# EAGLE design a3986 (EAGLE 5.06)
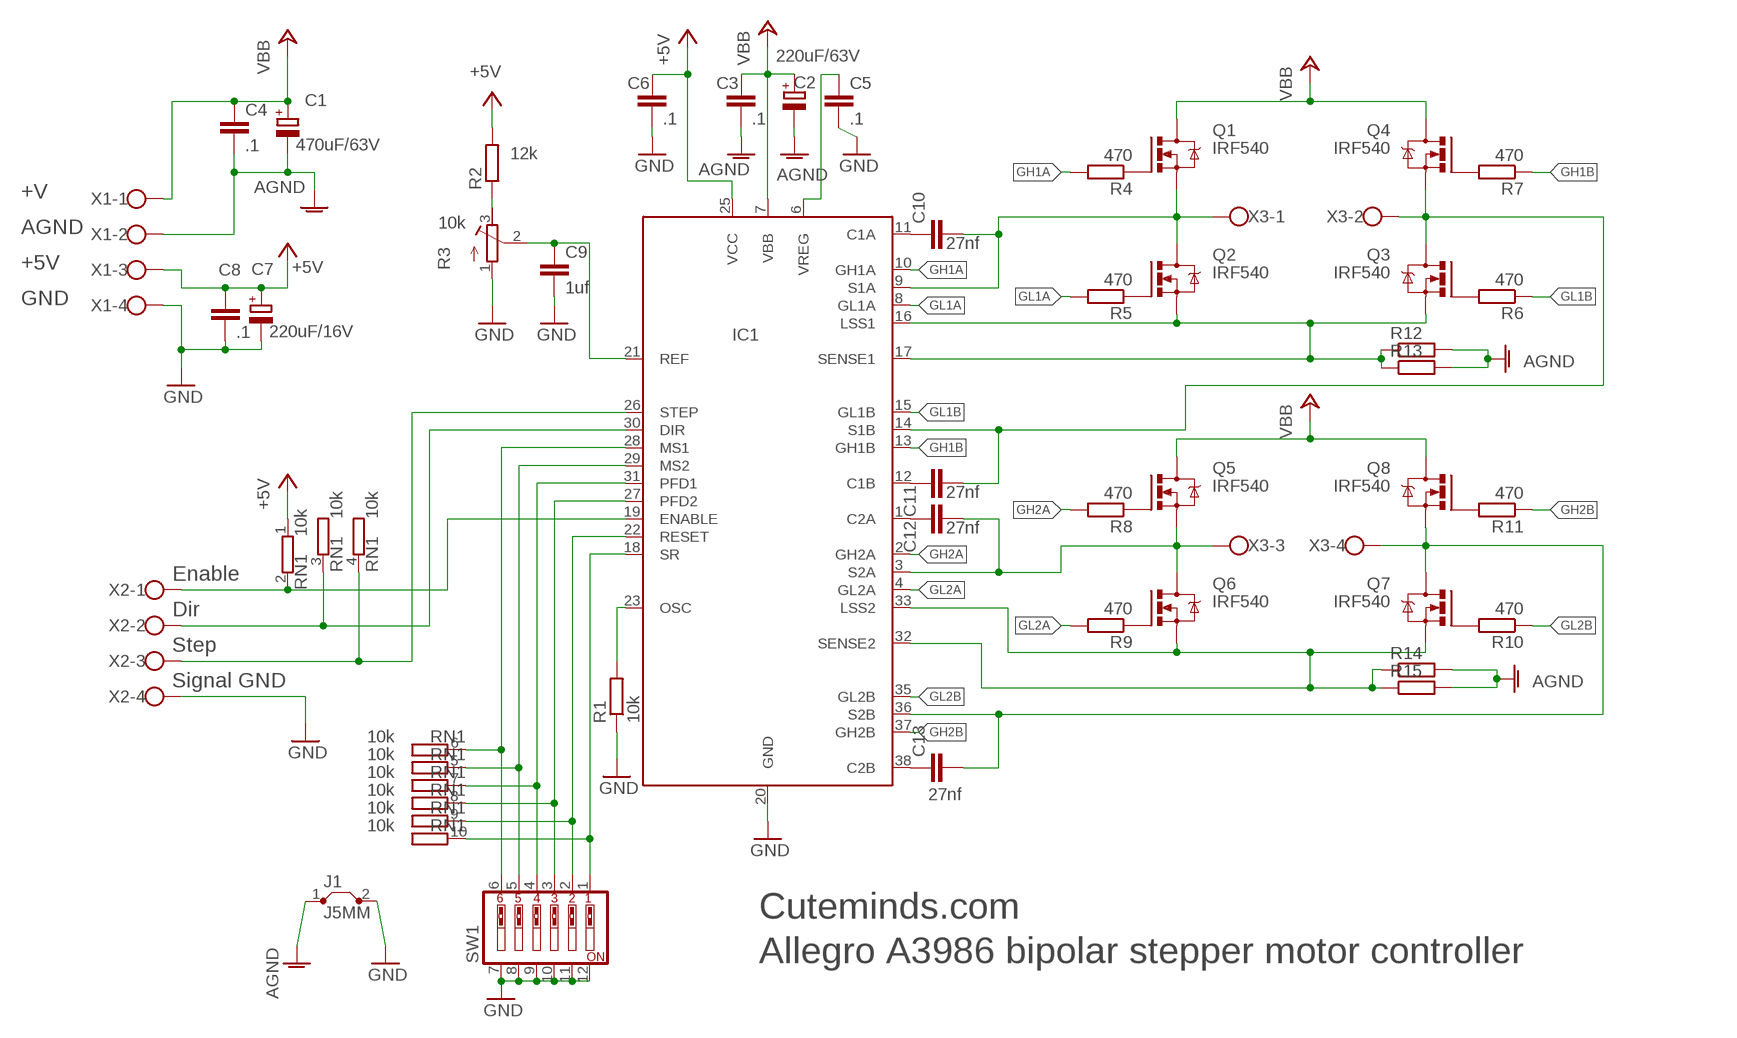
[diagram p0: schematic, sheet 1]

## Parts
C1  470uF/63V  CPOL-EUE5-10.5  [E5-10,5]
C2  220uF/63V  CPOL-EUE5-10.5  [E5-10,5]
C3  .1  C-EU050-024X044  [C050-024X044]
C4  .1  C-EU050-024X044  [C050-024X044]
C5  .1  C-EU050-024X044  [C050-024X044]
C6  .1  C-EU050-024X044  [C050-024X044]
C7  220uF/16V  CPOL-EUE5-8.5  [E5-8,5]
C8  .1  C-EU050-024X044  [C050-024X044]
C9  1uf  C-EU050-024X044  [C050-024X044]
C10  27nf  C-EU050-024X044  [C050-024X044]
C11  27nf  C-EU050-024X044  [C050-024X044]
C12  27nf  C-EU050-024X044  [C050-024X044]
C13  27nf  C-EU050-024X044  [C050-024X044]
IC1  A3986  [TSSOP38]
J1  J5MM  [05]
Q1  IRF540  [TO220BV]
Q2  IRF540  [TO220BV]
Q3  IRF540  [TO220BV]
Q4  IRF540  [TO220BV]
Q5  IRF540  [TO220BV]
Q6  IRF540  [TO220BV]
Q7  IRF540  [TO220BV]
Q8  IRF540  [TO220BV]
R1  10k  R-EU_0204/5  [0204/5]
R2  12k  R-EU_0204/5  [0204/5]
R3  10k  R-TRIMM64P  [RTRIM64P]
R4  470  R-EU_0204/5  [0204/5]
R5  470  R-EU_0204/5  [0204/5]
R6  470  R-EU_0204/5  [0204/5]
R7  470  R-EU_0204/5  [0204/5]
R8  470  R-EU_0204/5  [0204/5]
R9  470  R-EU_0204/5  [0204/5]
R10  470  R-EU_0204/5  [0204/5]
R11  470  R-EU_0204/5  [0204/5]
R12  R-EU_0207/15  [0207/15]
R13  R-EU_0207/15  [0207/15]
R14  R-EU_0207/15  [0207/15]
R15  R-EU_0207/15  [0207/15]
RN1  10k  GE09RP  [SIL10]
SW1  SW_DIP-6  [EDG-06]
X1  W237-4  [W237-4]
X2  W237-4  [W237-4]
X3  W237-4  [W237-4]

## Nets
+5V [5V]: C6.1 C7.+ C8.1 IC1.25(VCC) R2.2 RN1.1 X1.3
+24V [V+]: C1.+ C2.+ C3.1 C4.1 IC1.7(VBB) Q1.D Q4.D Q5.D Q8.D X1.1 ; supply symbol labelled VBB
AGND [AGND]: C1.- C2.- C3.2 C4.2 J1.1 R12.2 R13.2 R14.2 R15.2 X1.2
GH1A: IC1.10(GH1A) R4.2
GH1B: IC1.13(GH1B) R7.1
GH2A: IC1.2(GH2A) R8.2
GH2B: IC1.37(GH2B) R11.1
GL1A: IC1.8(GL1A) R5.2
GL1B: IC1.15(GL1B) R6.1
GL2A: IC1.4(GL2A) R9.2
GL2B: IC1.35(GL2B) R10.1
GND [GND]: C5.2 C6.2 C7.- C8.2 C9.2 IC1.20(GND) J1.2 R1.1 R3.1(E) SW1.7 SW1.8 SW1.9 SW1.10 SW1.11 SW1.12 X1.4 X2.4
N$1: IC1.27(PFD2) RN1.8 SW1.3
N$2: R2.1 R3.3(A)
N$3: IC1.28(MS1) RN1.6 SW1.6
N$4: C9.1 IC1.21(REF) R3.2(S)
N$5: IC1.29(MS2) RN1.5 SW1.5
N$6: IC1.23(OSC) R1.2
N$7: C5.1 IC1.6(VREG)
N$8: IC1.31(PFD1) RN1.7 SW1.4
N$10 [Motor]: IC1.16(LSS1) IC1.17(SENSE1) Q2.S Q3.S R12.1 R13.1
N$11 [Motor]: IC1.32(SENSE2) IC1.33(LSS2) Q6.S Q7.S R14.1 R15.1
N$12: Q1.G R4.1
N$13: Q2.G R5.1
N$14: Q3.G R6.2
N$15: Q4.G R7.2
N$16: Q5.G R8.1
N$17: IC1.18(SR) RN1.10 SW1.1
N$18: Q6.G R9.1
N$19: IC1.22(RESET) RN1.9 SW1.2
N$20: Q7.G R10.2
N$21: Q8.G R11.2
N$22: IC1.26(STEP) RN1.4 X2.3
N$23 [Motor]: C10.2 IC1.9(S1A) Q1.S Q2.D X3.1
N$24: IC1.30(DIR) RN1.3 X2.2
N$25: IC1.19(ENABLE) RN1.2 X2.1
N$26 [Motor]: C11.2 IC1.14(S1B) Q3.D Q4.S X3.2
N$27 [Motor]: C12.2 IC1.3(S2A) Q5.S Q6.D X3.3
N$28 [Motor]: C13.2 IC1.36(S2B) Q7.D Q8.S X3.4
N$30: C10.1 IC1.11(C1A)
N$31: C11.1 IC1.12(C1B)
N$32: C12.1 IC1.1(C2A)
N$33: C13.1 IC1.38(C2B)

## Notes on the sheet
- +V
- AGND
- +5V
- GND
- Enable
- Dir
- Step
- Signal GND
- Cuteminds.com
- Allegro A3986 bipolar stepper motor controller

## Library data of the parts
C1 C2 = resistor:CPOL-EU: POLARIZED CAPACITOR, European symbol
C3-C6 C8-C13 = resistor:C-EU: CAPACITOR, European symbol
C7 = rcl:CPOL-EU: POLARIZED CAPACITOR, European symbol
IC1 = allegro2:A3986: Dual Full-Bridge MOSFET Driver with Microstepping Translator
J1 = jumper:J: Bridge
Q1-Q8 = transistor-power:IRF540: HEXFET Power MOSFET
R1 R2 R4-R15 = rcl:R-EU_: RESISTOR, European symbol
R3 = rcl:R-TRIMM: Trimm resistor
RN1 = resistor-sil:GE09RP: SIL RESISTOR
SW1 = special:SW_DIP-6: DIP SWITCH
X1-X3 = con-wago-500:W237-4: WAGO SCREW CLAMP

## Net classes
1 V+: width 1.27 mm
2 GND: width 0.508 mm
3 AGND: width 1.778 mm
4 Motor: width 1.27 mm
5 5V: width 0.61 mm
6 none1: width 0.406 mm
7 none2: width 0.406 mm

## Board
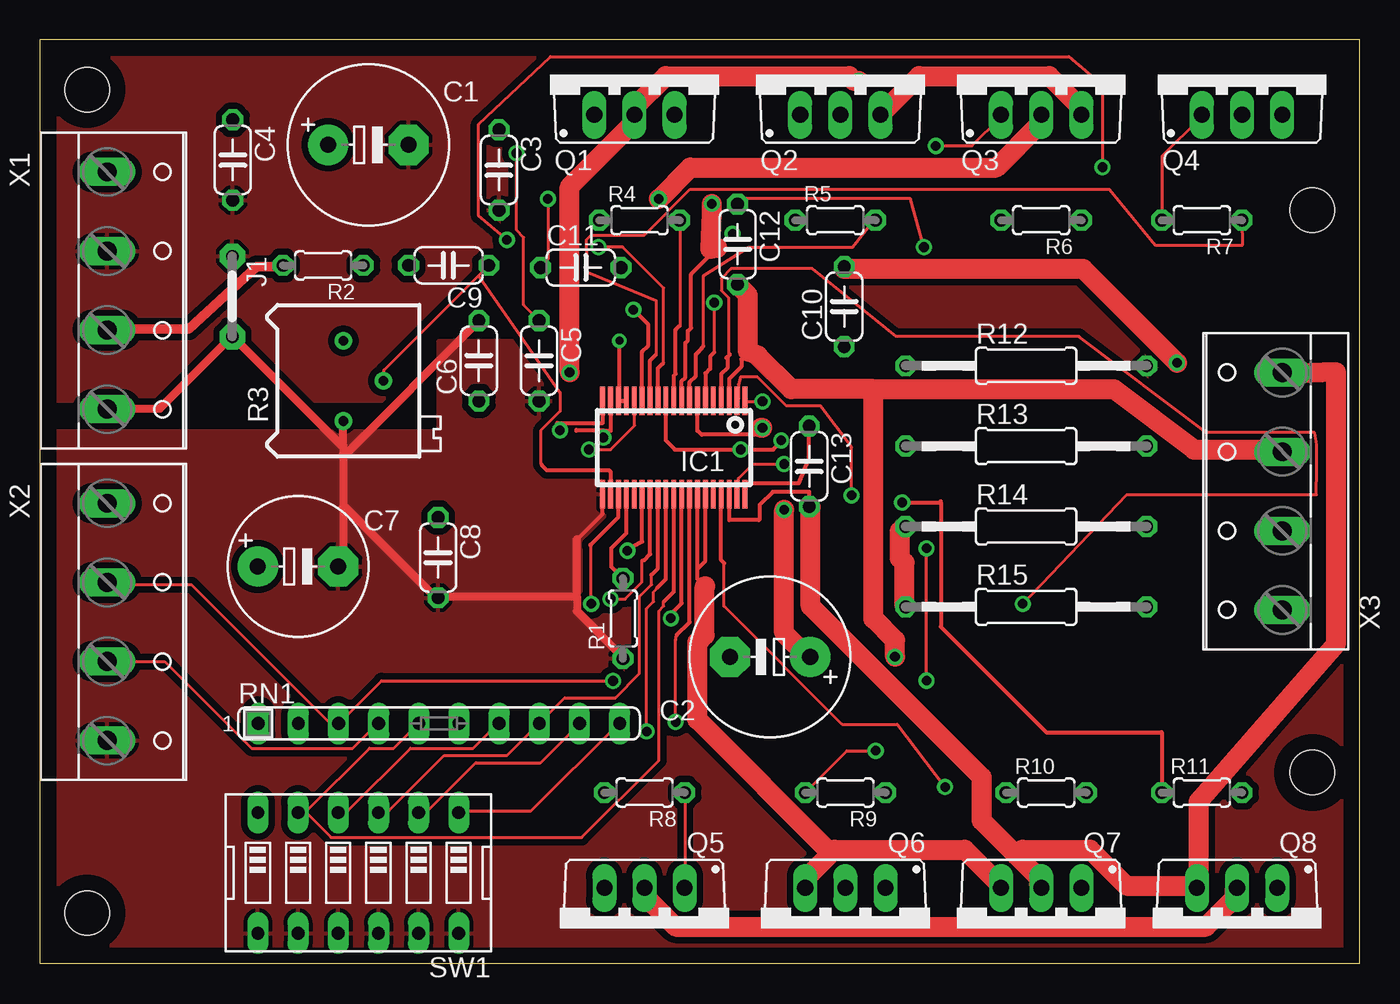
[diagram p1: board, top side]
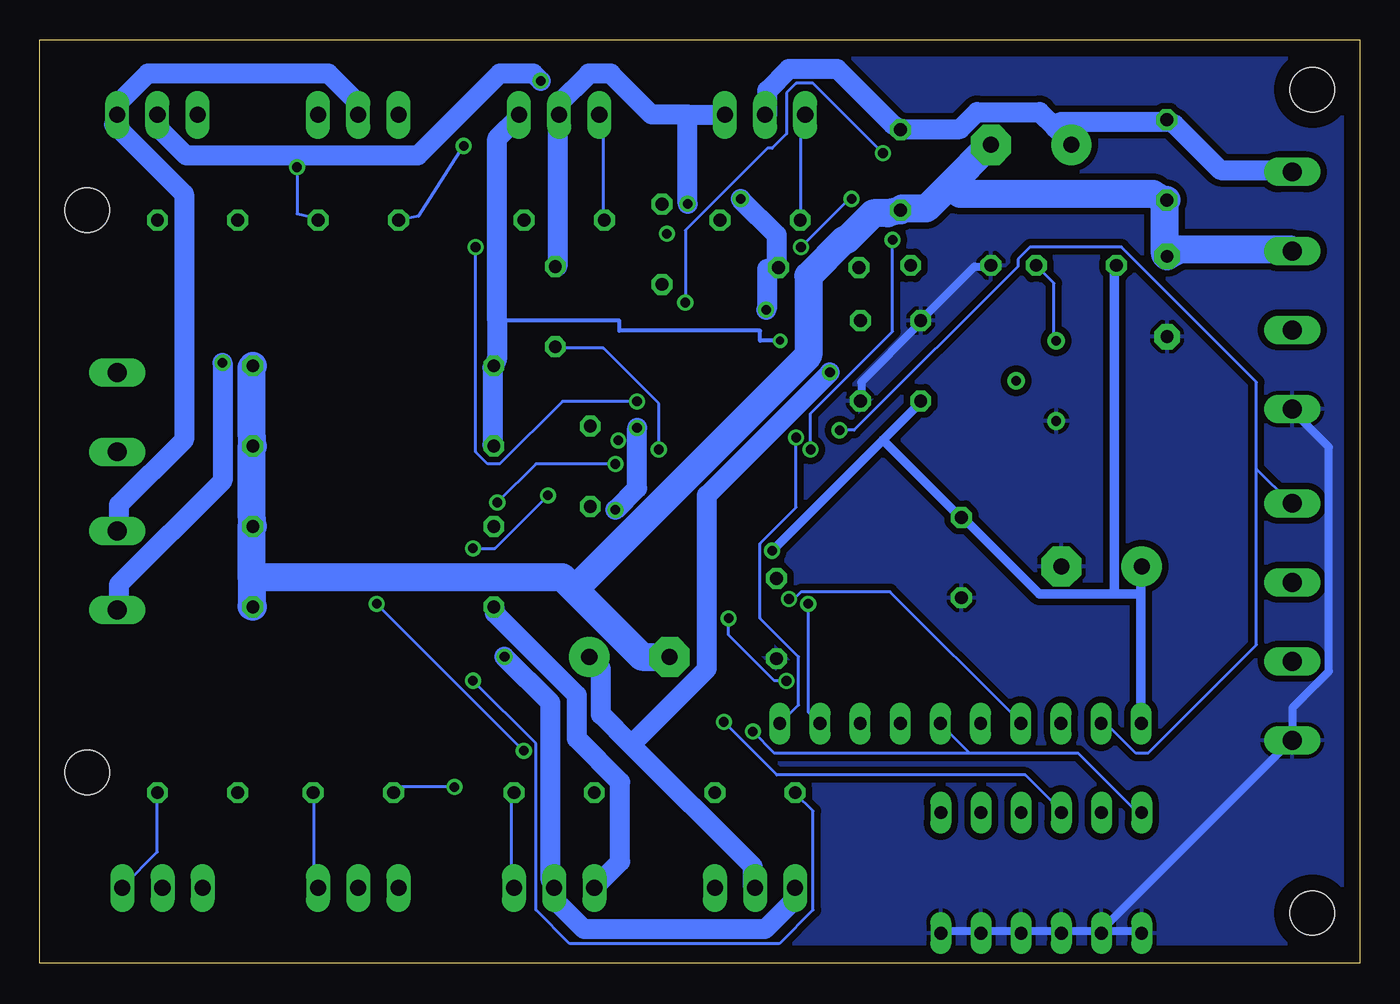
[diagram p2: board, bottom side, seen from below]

Size 83.49 x 58.41 mm. Coordinates in mm from the lower left corner, seen from the top.
Outline: 0,0 83.49,0 83.49,58.41 0,58.41 0,0
Copper layers (1*16): Top 0.035mm / dielectric 1.5mm / Bottom 0.035mm
Design rules "default *": minimum track width 8mil, minimum drill 24mil, track to track 6mil, track to pad 6mil, pad to pad 6mil, via to via 6mil, smd to smd 12mil, copper to edge 40mil, drill to drill 8mil, minimum pad ring 10mil, minimum via ring 8mil, stop-mask expansion 4mil, vias tented up to drill 0mil, thermal gap 10mil
Holes 2.8 mm at 3.01,55.24 80.48,47.62 80.48,12.06 3.01,3.17

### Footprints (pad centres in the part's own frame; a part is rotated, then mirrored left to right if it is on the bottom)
E5-10,5 = drill 1.016 pad 2.54 round: + -2.54,0 | drill 1.016 pad 2.54 octagon: - 2.54,0
C050-024X044 = drill 0.813 octagon: 1 -2.54,0; 2 2.54,0
E5-8,5 = drill 1.016 pad 2.54 round: + -2.54,0 | drill 1.016 pad 2.54 octagon: - 2.54,0
TSSOP38 = smd 0.3 x 1.8: 1 0,0; 2 0.5,0; 3 1,0; 4 1.5,0; 5 2,0; 6 2.5,0; 7 3,0; 8 3.5,0; 9 4,0; 10 4.5,0; 11 5,0; 12 5.5,0; 13 6,0; 14 6.5,0; 15 7,0; 16 7.5,0; 17 8,0; 18 8.5,0; 19 9,0; 20 9,5.9; 21 8.5,5.9; 22 8,5.9; 23 7.5,5.9; 24 7,5.9; 25 6.5,5.9; 26 6,5.9; 27 5.5,5.9; 28 5,5.9; 29 4.5,5.9; 30 4,5.9; 31 3.5,5.9; 32 3,5.9; 33 2.5,5.9; 34 2,5.9; 35 1.5,5.9; 36 1,5.9; 37 0.5,5.9; 38 0,5.9
05 = drill 0.813 pad 1.6 octagon: 1 -2.54,0; 2 2.54,0
TO220BV = drill 1.016 long: D 0,-2.54; G -2.54,-2.54; S 2.54,-2.54
0204/5 = drill 0.813 octagon: 1 -2.54,0; 2 2.54,0
RTRIM64P = drill 0.61 round: 1 0,-2.54; 2 2.54,0; 3 0,2.54
0207/15 = drill 0.813 octagon: 1 -7.62,0; 2 7.62,0
SIL10 = drill 0.813 long: 1 -11.43,0; 2 -8.89,0; 3 -6.35,0; 4 -3.81,0; 5 -1.27,0; 6 1.27,0; 7 3.81,0; 8 6.35,0; 9 8.89,0; 10 11.43,0
EDG-06 = drill 0.813 long: 1 -6.35,-3.81; 2 -3.81,-3.81; 3 -1.27,-3.81; 4 1.27,-3.81; 5 3.81,-3.81; 6 6.35,-3.81; 7 6.35,3.81; 8 3.81,3.81; 9 1.27,3.81; 10 -1.27,3.81; 11 -3.81,3.81; 12 -6.35,3.81
W237-4 = drill 1.194 long: 1 -7.5,-1.27; 2 -2.5,-1.27; 3 2.5,-1.27; 4 7.5,-1.27

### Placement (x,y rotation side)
C1  20.79,51.75 0 top
C2  46.19,19.36 180 top
C3  29.05,50.16 270 top
C4  12.22,50.8 270 top
C5  31.59,38.1 270 top
C6  27.78,38.1 90 top
C7  16.35,25.08 0 top
C8  25.2,25.65 270 top
C9  25.87,44.13 180 top
C10  50.88,41.52 90 top
C11  34.22,43.99 0 top
C12  44.14,45.46 270 top
C13  48.67,31.42 270 top
IC1  44.6,35.55 180 top
J1  12.19,42.16 270 top
Q1  37.62,56.19 0 top
Q2  50.63,56.19 0 top
Q3  63.34,56.19 0 top
Q4  76.03,56.19 0 top
Q5  38.25,2.22 180 top
Q6  50.95,2.22 180 top
Q7  63.34,2.22 180 top
Q8  75.72,2.22 180 top
R1  36.88,21.8 90 top
R2  17.93,44.13 180 top
R3  19.2,36.83 0 top
R4  37.94,46.98 0 top
R5  50.32,46.98 0 top
R6  63.34,46.98 180 top
R7  73.49,46.98 180 top
R8  38.25,10.79 180 top
R9  50.95,10.79 180 top
R10  63.65,10.79 0 top
R11  73.49,10.79 0 top
R12  62.38,37.78 0 top
R13  62.38,32.7 0 top
R14  62.38,27.62 0 top
R15  62.38,22.54 0 top
RN1  25.25,15.16 0 top
SW1  20.16,5.71 180 top
X1  5.55,42.54 270 top
X2  5.55,21.58 270 top
X3  77.3,29.84 90 top

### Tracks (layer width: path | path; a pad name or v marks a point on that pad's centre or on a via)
+5V  (via drill 0.61)
  Top 0.254: IC1.25 38.1,26.66 37.09,26.13
  Top 0.61: R2.2 15.38,44.06 13.72,44.06 9.44,40.1 4.41,40.1 X1.3 | v37.17,26.08 37.22,26.08 37.09,26.13
  Bottom 0.61: 13.86,23.34 13.86,25.01 C7.+ | 13.86,23.34 13.86,15.26 RN1.1 | 30.16,33.09 27.72,35.53 C6.1 | 30.16,33.09 v37.17,26.08 | 30.16,33.09 25.29,28.21 C8.1 24.98,28.06 20.26,23.34 15.53,23.34 | 13.86,23.34 15.53,23.34 | R2.2 15.53,44.06 15.53,23.34
+24V  (via drill 0.61)
  Top 0.254: IC1.7 41.6,33.68 41.86,33.43 45.18,33.43 45.63,33.87
  Top 1.27: v47.08,28.67 47.08,20.9 48.6,19.38 C2.+ | v45.71,33.85 45.63,33.87 | Q8.D 75.58,4.75 75.58,4.13 73.75,2.31 40.22,2.31 38.39,4.13 38.39,4.75 Q5.D | v51.8,55.8 51.5,55.8 51.19,56.1 39.61,56.1 37.63,54.12 37.63,53.66 Q1.D 37.48,53.06 33.52,49.09 v33.52,37.36
  Bottom 1.27: v45.71,33.85 45.71,30.04 v47.08,28.67 | 46.09,13.81 47.99,15.72 47.99,18.61 48.6,19.22 C2.+ | 46.09,13.81 38.39,6.12 38.39,4.9 Q5.D | 19.27,52.83 18.28,51.84 C1.+ | 19.27,52.83 20.26,53.82 24.22,53.82 25.29,52.75 28.94,52.75 C3.1 29.55,53.06 33.06,56.56 36.11,56.56 37.48,55.19 37.48,53.66 Q1.D | 19.27,52.83 18.89,53.21 12.33,53.21 C4.1 11.72,53.06 8.83,50.16 4.41,50.16 X1.1 | v51.8,55.8 52.26,56.26 54.39,56.26 59.58,51.07 74.21,51.07 76.03,52.9 Q4.D | v33.52,37.36 41.29,29.59 41.29,18.61 46.09,13.81
AGND
  Bottom 1.778: 12.33,48.18 12.33,44.83 J1.1 11.42,45.13 4.41,45.13 X1.2 | 12.33,48.18 C4.2 | 25.89,49.25 23.46,51.68 C1.- | 25.89,49.25 27.42,47.72 28.94,47.72 C3.2 29.86,47.42 30.77,47.42 32.45,45.74 32.6,45.74 34.89,43.45 34.89,38.43 49.67,23.64 | 12.33,48.18 13.09,48.64 25.29,48.64 25.89,49.25 | 70.09,24.4 70.09,27.61 R14.2 70.09,28.37 70.09,32.63 R13.2 70.09,33.55 70.09,37.66 R12.2 | 70.09,24.4 70.09,22.58 R15.2 | 49.67,23.64 50.43,24.4 70.09,24.4 | 49.67,23.64 45.4,19.38 43.73,19.38 C2.-
  pour Top (isolate 0.406): 1.1,57.78 83.02,57.78 83.02,35.55 1.1,35.55
GH1A
  Top 0.203: 40.48,40.31 40.53,40.41 40.53,46.96 R4.2
  Top 0.254: IC1.10 40.1,37.15 40.22,37.27 40.22,40.05 40.48,40.31
GH1B
  Top 0.203: 38.95,38.45 39,38.43 39,41.88 34.65,43.67 34.58,45.74 34.89,46.05 38.24,46.05 41.13,48.94 67.65,48.94 70.55,45.41 76.07,45.41 76.03,46.96 R7.1
  Top 0.254: IC1.13 38.6,38.11 38.95,38.45
GH2A  (via drill 0.61)
  Top 0.203: v51.35,29.59 51.35,32.63 49.38,35.24 47.22,35.24 45.39,37.07 44.34,37.07 44.18,36.6 44.18,35.68 IC1.2 | v56.08,17.86 v56.08,26.23
  Bottom 0.203: v51.35,29.59 54.7,26.23 v56.08,26.23 | v56.08,17.86 52.11,13.89 52.11,3.37 49.98,1.24 36.72,1.24 34.58,3.37 34.58,9.62 35.65,10.69 R8.2
GH2B  (via drill 0.61)
  Top 0.203: v47.08,31.57 45.1,31.57 44.18,30.65 44.18,29.74 IC1.37 | R11.1 70.85,10.84
  Top 0.254: v54.55,29.13 56.98,29.13 | 56.98,29.13 56.98,29.2 | 56.98,29.13 56.98,21.27 63.65,14.6 70.95,14.6 R11.1
  Bottom 0.203: v47.08,31.57 52.11,31.57 v54.55,29.13
GL1A
  Top 0.203: 41.97,39.03 41.97,43.47 44.86,45.27 51.41,45.27 52.72,46.96 R5.2
  Top 0.254: IC1.8 41.1,36.73 41.51,37.14 41.51,38.49 41.97,39.03 41.6,38.59
GL1B  (via drill 0.61)
  Top 0.203: v34.73,32.48 36.11,32.48 37.63,34.01 37.63,35.53 IC1.15 | v29.55,45.74 27.77,47.26 27.77,53.06 32.31,57.34 65.07,57.34 67.21,55.52 v67.21,50.34
  Bottom 0.203: v34.73,32.48 34.73,34.77 29.55,39.95 v29.55,45.74 | v67.21,50.34 67.21,47.39 65.98,47.11 R6.1
GL2A  (via drill 0.61)
  Top 0.203: v62.17,22.73 68.74,29.62 80.73,29.62 80.76,31.24 80.76,32.79 80.63,33.55 73.79,33.55 65.73,39.62 54.19,39.62 48.88,43.91 43.73,43.91 43.12,43.3 43.12,42.54 43.57,42.08 43.57,38.58 43.66,38.5 | v52.87,13.43 51.04,13.43 48.45,10.84 R9.2
  Top 0.254: IC1.4 43.1,37.24 43.49,37.62 43.49,38.33 43.66,38.5 43.43,38.27
  Bottom 0.203: v52.87,13.43 v62.17,22.73
GL2B  (via drill 0.61)
  Top 0.203: v57.25,11.15 54.24,15.11 50.74,15.11 43.27,22.58 43.27,25.17 43.3,25.29
  Top 0.254: IC1.35 43.1,25.48 43.3,25.29
  Bottom 0.203: v57.25,11.15 60.8,11.15 61.1,10.84 R10.1
GND
  Top 0.254: IC1.20 35.6,28.42 33.98,26.79
  Top 0.508: 33.97,23.18 33.97,22.27 36.87,19.38 R1.1 | 33.97,23.18 33.97,26.69 33.98,26.79 | 33.97,23.18 25.29,23.18 C8.2 24.98,23.18 19.34,28.82 19.19,28.82 | 19.19,28.82 19.19,25.47 18.89,25.17 C7.- | 19.19,32.18 19.19,28.82 | 19.19,32.79 19.19,32.18 | 19.19,32.79 19.19,34.16 R3.1 | 19.19,32.79 19.04,32.79 12.33,39.49 J1.2 12.03,39.49 7.61,35.07 4.41,35.07 X1.4 | C6.2 27.72,40.56 19.34,32.18 19.19,32.18
  Bottom 0.508: SW1.7 13.86,2 16.29,2 SW1.8 | SW1.8 16.45,2 18.89,2 SW1.9 19.04,2 21.32,2 SW1.10 21.63,2 23.91,2 SW1.11 24.07,2 26.51,2 SW1.12 | SW1.8 16.29,2.15 4.41,14.04 X2.4 4.25,14.35 4.25,16.18 1.97,18.46 1.97,32.63 4.25,34.92 X1.4 | C9.2 23.46,44.06 24.37,44.06 27.72,40.71 C6.2 27.88,40.41 31.53,36.75 31.53,35.68 C5.2
  pour Top (isolate 0.406): 1.1,33.65 25.23,33.65 25.23,39.37 83.02,39.37 83.02,0.63 1.1,0.63
  pour Bottom (isolate 0.406): 1.1,57.78 82.38,57.78 82.38,1.27 1.1,1.27
N$1
  Top 0.203: SW1.3 21.48,9.62 22.09,9.62 25.59,13.13 29.55,13.13 31.53,15.11 RN1.8 31.69,15.26 33.21,16.78 36.41,16.78 37.94,18.31 37.94,23.18 38.7,23.95 38.7,24.56 38.69,24.56
  Top 0.254: IC1.27 39.1,24.97 38.69,24.56
N$2
  Bottom 0.203: R3.3 19.34,39.49 19.34,43 R2.1
N$3  (via drill 0.61)
  Top 0.203: v38.39,14.65 38.39,22.42 38.84,22.87 38.84,23.48 39.13,23.82
  Top 0.254: IC1.28 39.6,24.29 39.13,23.82 39.07,23.76
  Bottom 0.203: 24.68,13.28 17.82,13.28 14.16,9.62 13.86,9.62 SW1.6 | 24.68,13.28 26.51,15.11 RN1.6 | v38.39,14.65 37.02,13.28 24.68,13.28
N$4
  Top 0.203: 27.75,43.48 28.33,44.06 C9.1 | 27.75,43.48 21.78,37.51 21.78,36.9 R3.2 | 27.75,43.48 32.92,36.09 32.92,34.91 31.69,33.68 31.69,31.57 31.74,31.51
  Top 0.254: IC1.21 36.1,31.08 36,31.19 32.07,31.19 31.74,31.51
N$5
  Top 0.203: 16.75,9.62 16.9,9.62 20.87,13.58 22.39,13.58 23.91,15.11 RN1.5 | 16.75,9.62 16.45,9.62 SW1.5 16.75,9.62 | 16.75,9.62 18.43,7.95 34.28,7.95 39.15,12.82 39.15,22.27 39.46,22.58 39.46,22.88 39.49,22.89
  Top 0.254: IC1.29 40.1,23.5 39.49,22.89
N$6
  Top 0.254: IC1.23 37.1,27.19 36.16,26.25 36.16,25.06 R1.2
N$7  (via drill 0.61)
  Top 0.203: v30.16,51.23 30.16,46.35 30.62,45.89 30.62,41.63 31.53,40.71 C5.1 | v42.66,41.78 42.66,38.62
  Top 0.254: IC1.6 42.1,37.29 42.4,37.59 42.4,38.36 42.66,38.62
  Bottom 0.203: v42.66,41.78 42.66,46.35 37.48,51.53 37.17,51.53 36.26,52.45 36.26,55.04 35.65,55.65 34.58,55.65 v30.16,51.23
N$8  (via drill 0.61)
  Top 0.203: SW1.4 18.89,9.62 19.5,9.62 23.46,13.58 27.42,13.58 28.94,15.11 RN1.7 | v40.22,15.26 40.22,20.42 40.29,20.74
  Top 0.254: IC1.31 41.1,21.56 40.29,20.74
  Bottom 0.203: v40.22,15.26 36.87,11.91 21.17,11.91 18.89,9.62 SW1.4
N$10  (via drill 0.5)
  Top 0.254: IC1.17 IC1.16 36.66,35.55 v36.66,39.37
  Top 1.27: Q3.S 65.82,53.66 65.82,54.12 63.84,56.1 55.61,56.1 53.18,53.66 Q2.S
  Bottom 0.254: v36.66,39.37 37.94,39.37 37.94,40 46.83,40 46.83,40.64 54.55,40.64
  Bottom 1.27: R13.1 54.85,32.79 54.85,37.66 R12.1 54.55,38.27 54.55,40.64 54.55,52.14 53.18,53.51 Q2.S
N$11
  Top 0.254: 41.6,24.94 41.6,24.33 42.09,23.84 42.12,23.81 | 41.6,24.94 IC1.32 | IC1.33 42.1,25.44 41.6,24.94
  Top 1.27: R15.1 54.7,22.58 54.7,25.32 54.39,25.62 54.39,27.3 54.7,27.61 R14.1 | 50.05,6.96 50.28,7.18 58.51,7.18 60.8,4.9 Q7.S | 50.05,6.96 48.45,5.35 48.45,4.9 Q6.S | 42.09,23.84 42.05,23.79 42.05,20.75 41.59,20.29 41.59,15.41 50.05,6.96
  Bottom 1.27: R15.1 54.7,22.42 54.7,22.12 49.52,16.94 49.52,14.19 46.77,11.45 46.77,6.42 48.3,4.9 Q6.S
N$12
  Bottom 0.203: R4.1 35.34,47.11 35.34,53.36 35.19,53.51 Q1.G
N$13
  Bottom 0.203: R5.1 47.84,47.11 47.84,53.36 47.99,53.51 Q2.G
N$14  (via drill 0.61)
  Top 0.203: v56.67,51.68 58.97,51.68 60.8,53.51 Q3.G
  Bottom 0.203: v56.67,51.68 59.52,47.24 R6.2
N$15
  Top 0.203: R7.2 71.01,47.11 71.01,51.07 73.44,53.51 Q4.G
N$16
  Top 0.203: R8.1 40.83,10.69 40.83,4.9 Q5.G
N$17  (via drill 0.61)
  Top 0.203: v35.65,33.24 35.65,33.68 35.65,33.7 | SW1.1 26.51,9.62 31.08,9.62 36.56,15.11 RN1.10
  Top 0.254: IC1.18 36.12,35.55 36.12,33.68 35.65,33.68 33.95,33.68 33.95,33.72
  Bottom 0.203: v35.65,33.24 35.65,28.82 37.94,26.54 37.94,21.81 35.5,19.38 35.5,16.33 36.56,15.26 RN1.10
N$18
  Bottom 0.203: R9.1 53.63,10.69 53.63,4.9 Q6.G
N$19  (via drill 0.61)
  Top 0.203: v34.89,22.73 34.89,26.39 34.83,26.45 | SW1.2 24.07,9.62 24.52,9.62 27.57,12.67 31.69,12.67 34.12,15.11 RN1.9
  Top 0.254: IC1.22 36.6,28.22 34.83,26.45 34.82,26.44
  Bottom 0.203: v34.89,22.73 34.89,15.87 34.28,15.26 RN1.9
N$20
  Bottom 0.203: R10.2 66.13,10.69 66.13,5.05 65.98,4.9 Q7.G
N$21
  Bottom 0.203: R11.2 76.03,7.03 78.17,4.9 Q8.G
N$22  (via drill 0.61)
  Top 0.203: v36.11,23.03 37.02,23.03 38.09,24.1 38.09,25.47 38.21,25.48 | X2.3 4.41,19.07 7.91,19.07 13.4,13.58 19.8,13.58 21.32,15.11 RN1.4
  Top 0.254: IC1.26 38.6,25.87 38.21,25.48
  Bottom 0.203: v36.11,23.03 35.8,23.03 35.34,23.49 29.71,23.49 21.48,15.26 RN1.4
N$23  (via drill 0.61)
  Top 0.254: IC1.9 40.6,36.82 40.83,37.04 40.83,39.23 40.99,39.39 40.99,39.98 41.19,40.18 41.19,43.57 42.86,45.24 43.76,46.13
  Top 1.27: v71.92,37.97 65.98,43.91 50.89,43.91 C10.2 | v42.51,48.03 42.51,47.45 42.42,45.16 42.86,45.24
  Bottom 1.27: C10.2 50.74,44.06 50.74,53.51 Q2.D 50.74,54.28 48.76,56.26 47.38,56.26 44.79,53.66 42.51,53.66 | 42.51,53.66 40.22,53.66 Q1.S | v71.92,37.97 71.92,30.5 78.47,23.95 78.47,22.42 X3.1 | v42.51,48.03 42.51,53.66
N$24  (via drill 0.61)
  Top 0.203: X2.2 4.41,23.95 9.59,23.95 18.28,15.26 18.89,15.26 RN1.3 19.04,15.26 21.63,17.85 v36.26,17.85 | v39.92,21.81 39.92,21.97 39.86,22.02
  Top 0.254: IC1.30 40.6,22.76 39.86,22.02 40.09,21.93
  Bottom 0.203: v39.92,21.81 39.92,20.75 37.02,17.85 v36.26,17.85
N$25  (via drill 0.61)
  Top 0.203: v32.91,33.7 32.73,33.7
  Top 0.254: IC1.19 35.62,35.55 35.62,34.17 32.73,34.17 32.73,33.7 32.73,33.68
  Bottom 0.203: v32.91,33.7 31.99,33.7 21.63,44.06 21.63,44.52 20.87,45.28 15.08,45.28 6.54,36.75 6.54,31.26 | 6.54,31.26 4.41,29.13 X2.1 | 6.54,31.26 6.54,20.14 13.4,13.28 14.16,13.28 15.99,15.11 16.29,15.11 RN1.2
N$26  (via drill 0.6, 0.61)
  Top 0.254: IC1.14 38.1,38.67 38.5,39.06 38.5,40.38 v37.54,41.33
  Top 1.27: v39.15,48.33 41.13,50.31 60.49,50.31 63.23,53.06 63.23,53.51 Q3.D
  Bottom 1.27: v39.15,48.33 36.87,46.05 36.87,44.06 C11.2 37.48,43.91 37.48,41.47 v37.54,41.33 | Q3.D 63.39,53.66 63.39,54.43 65.21,56.26 76.64,56.26 78.47,54.43 78.47,53.66 Q4.S 78.78,53.06 74.36,48.64 74.36,33.09 78.47,28.98 78.47,27.45 X3.2
N$27  (via drill 0.61)
  Top 0.254: IC1.3 43.6,36.94 44.38,37.72 44.38,38.2 44.86,38.67 44.93,38.74
  Top 1.27: C12.2 44.18,42.85 44.79,42.23 44.79,38.73 44.86,38.67 45.4,38.43 47.54,36.29 52.72,36.29 | 52.72,36.29 67.93,36.29 73.01,32.48 78.47,32.48 X3.3 | v54.09,19.38 54.09,20.42 52.72,21.79 52.72,36.29
  Bottom 1.27: Q5.S 35.8,4.75 35.8,3.98 37.63,2.15 49.06,2.15 50.89,3.98 50.89,4.75 Q6.D 51.19,5.35 51.19,16.48 v54.09,19.38
N$28
  Top 0.254: C13.2 48.67,29.8 46.37,29.8 45.54,28.98 45.54,28.08 45.47,28.01 43.62,28.01 43.62,29.64 IC1.36
  Top 1.27: 61.79,6.8 63.23,5.35 63.23,4.9 Q7.D | 61.79,6.8 59.58,9.01 59.58,11.76 48.76,22.58 48.76,28.82 C13.2 | 61.79,6.8 62.17,7.18 66.43,7.18 68.72,4.9 73.14,4.9 Q8.S 73.29,5.51 73.29,10.23 81.99,20.2 81.99,37.37 78.63,37.24 78.63,37.21 X3.4
N$29  (via drill 0.6)
  other vias: 46.9,33.06
N$30  (via drill 0.61)
  Top 0.254: IC1.11 39.6,33.05 40.17,32.48 v44.34,32.48 46.38,32.48 46.9,33
  Bottom 0.203: v44.34,32.48 44.34,35.38 47.84,38.88 50.74,38.88 C10.1
N$31  (via drill 0.61)
  Top 0.203: v35.34,45.28 36.87,45.28 39.46,42.69 39.46,37.97 39.39,37.91 | v32.14,48.33 32.14,44.52 31.69,44.06 C11.1
  Top 0.254: IC1.12 39.1,37.62 39.39,37.91
  Bottom 0.203: v35.34,45.28 32.3,48.33 v32.14,48.33
N$32  (via drill 0.61)
  Top 0.203: v45.71,35.53 44.64,35.53 IC1.1 | v55.92,45.28 55.08,48.34 44.18,48.34 C12.1
  Bottom 0.203: v45.71,35.53 50.43,35.53 54.39,31.57 55.16,31.57 55.92,32.33 v55.92,45.28
N$33
  Top 0.254: C13.1 48.64,33.94 48.64,31.92 48.02,30.36 44.62,30.36 44.61,30.35 44.61,29.66 IC1.38
N$35  (via drill 0.6)
  other vias: 43.82,46.13

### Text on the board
tDocu: IRF540 | IRF540 | IRF540 | IRF540 | .1uF | 470uF/63V | .1uF | +V | 470 | 470 | 470 | 470 | 12k | 1uF | AGND | 27nF | 27nF | 27nF | +5V | GND | .1uF | .1uF | 10k | A3986 | 27nF | En | 220uf/63V | Dir | .1uF | A A- B B- | 10k | Step | 220uF/16V | GND | 10k | MS1 | MS2 | Pfd1 | Pfd2 | RS | SR | 470 | 470 | 470 | 470 | IRF540 | IRF540 | IRF540 | IRF540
